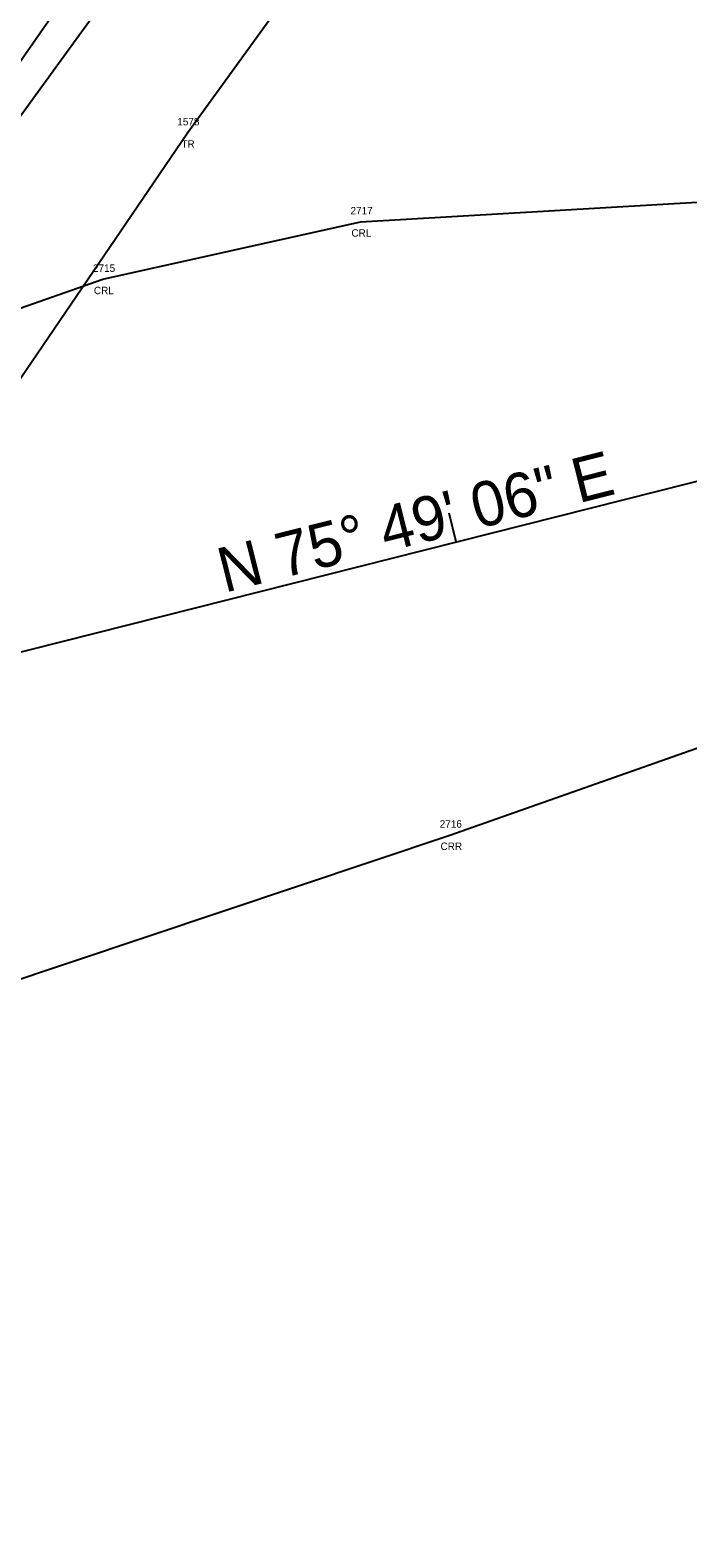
# Model space of a CAD drawing. Extents: x 2266664 to 2272542, y 716533 to 724777.
# Drawn here: x 2267700.4 to 2267788.8, y 717769.3 to 717971.9 of the extents above; entities that cross this region are included whole.
import ezdxf

# ---------------------------------------------------------------- set-up
doc = ezdxf.new("R2010")
doc.units = 0
for name, color, linetype in [('RD_EX_GuardRail', 7, 'Continuous'), ('RD_EX_H2O', 7, 'Continuous'), ('RD_EX_H2O_txCode', 7, 'Continuous'), ('RD_EX_Road', 7, 'Continuous'), ('RD_EX_VEG', 7, 'Continuous'), ('RD_EX_VEG_txCode', 7, 'Continuous'), ('RD_HC_Cl', 7, 'Continuous'), ('RD_HC_Data', 7, 'Continuous'), ('RD_HC_Data_Tic', 7, 'Continuous'), ('RD_SMD_Locator', 7, 'Continuous')]:
    doc.layers.add(name, color=color, linetype=linetype)

msp = doc.modelspace()

# ---------------------------------------------------------------- linework, layer by layer
at = {"layer": 'RD_EX_GuardRail'}
msp.add_lwpolyline([(2267506.03, 717677.39), (2267559.71, 717759.86), (2267580, 717788.93), (2267679.56, 717933.57), (2267740.09, 718016.9), (2267757.63, 718042.07)], dxfattribs=at)
at = {"layer": 'RD_EX_H2O'}
for points in [[(2267648.67, 717950.99), (2267680, 717930.6), (2267687.12, 717930.39), (2267710.19, 717938.44), (2267744.82, 717946.17), (2267816.91, 717950.39), (2267875.61, 717952.39), (2267928.18, 717957.12), (2267936.35, 717960.67), (2267968.01, 717966.35), (2267984.51, 717962.62), (2267996.02, 717960.08)], [(2267591.63, 717899.51), (2267637.77, 717865.9), (2267685.44, 717839.85), (2267756.83, 717863.74), (2267826.13, 717888.16), (2267866.36, 717887.16), (2267930.84, 717899.12), (2268026.36, 717789.97), (2268079.49, 717725.08)]]:
    msp.add_lwpolyline(points, dxfattribs=at)
at = {"layer": 'RD_EX_Road'}
msp.add_lwpolyline([(2267679.35, 717936.13), (2267677.75, 717937.24), (2267696.23, 717963.72), (2267735.24, 718019.64), (2267790.98, 718100.9), (2267816.93, 718136.13), (2267852.97, 718190.65)], dxfattribs=at)
at = {"layer": 'RD_EX_VEG'}
msp.add_lwpolyline([(2267330.42, 717346.12), (2267314.92, 717369.68), (2267464.99, 717583.46), (2267551.97, 717708.99), (2267721.53, 717958.13), (2267810.77, 718081.35), (2267867.02, 718039.18)], dxfattribs=at)
at = {"layer": 'RD_HC_Cl'}
msp.add_line((2267686.28, 717885.1), (2267821.52, 717919.27), dxfattribs=at)
at = {"layer": 'RD_HC_Data_Tic'}
msp.add_line((2267757.69, 717903.14), (2267756.71, 717907.02), dxfattribs=at)
at = {"layer": 'RD_SMD_Locator'}
for centre in [(2267721.53, 717958.13), (2267744.82, 717946.17), (2267710.19, 717938.44), (2267756.83, 717863.74)]:
    msp.add_circle(centre, 0.001, dxfattribs=at)

# ---------------------------------------------------------------- texts
at = {"layer": 'RD_EX_H2O_txCode'}
for s, p in [('2717', (2267743.47, 717947.17)), ('CRL', (2267743.59, 717944.17)), ('2715', (2267708.85, 717939.44)), ('CRL', (2267708.97, 717936.44)), ('2716', (2267755.46, 717864.74)), ('CRR', (2267755.57, 717861.74))]:
    msp.add_text(s, height=1, dxfattribs=at).set_placement(p)
at = {"layer": 'RD_EX_VEG_txCode'}
for s, p in [('1578', (2267720.18, 717959.13)), ('TR', (2267720.73, 717956.13))]:
    msp.add_text(s, height=1, dxfattribs=at).set_placement(p)
at = {"layer": 'RD_HC_Data'}
msp.add_text('N 75%%d 49\' 06" E', height=6, rotation=14.1816, dxfattribs=at).set_placement((2267726.53, 717896.3))

doc.saveas('drawing.dxf')
